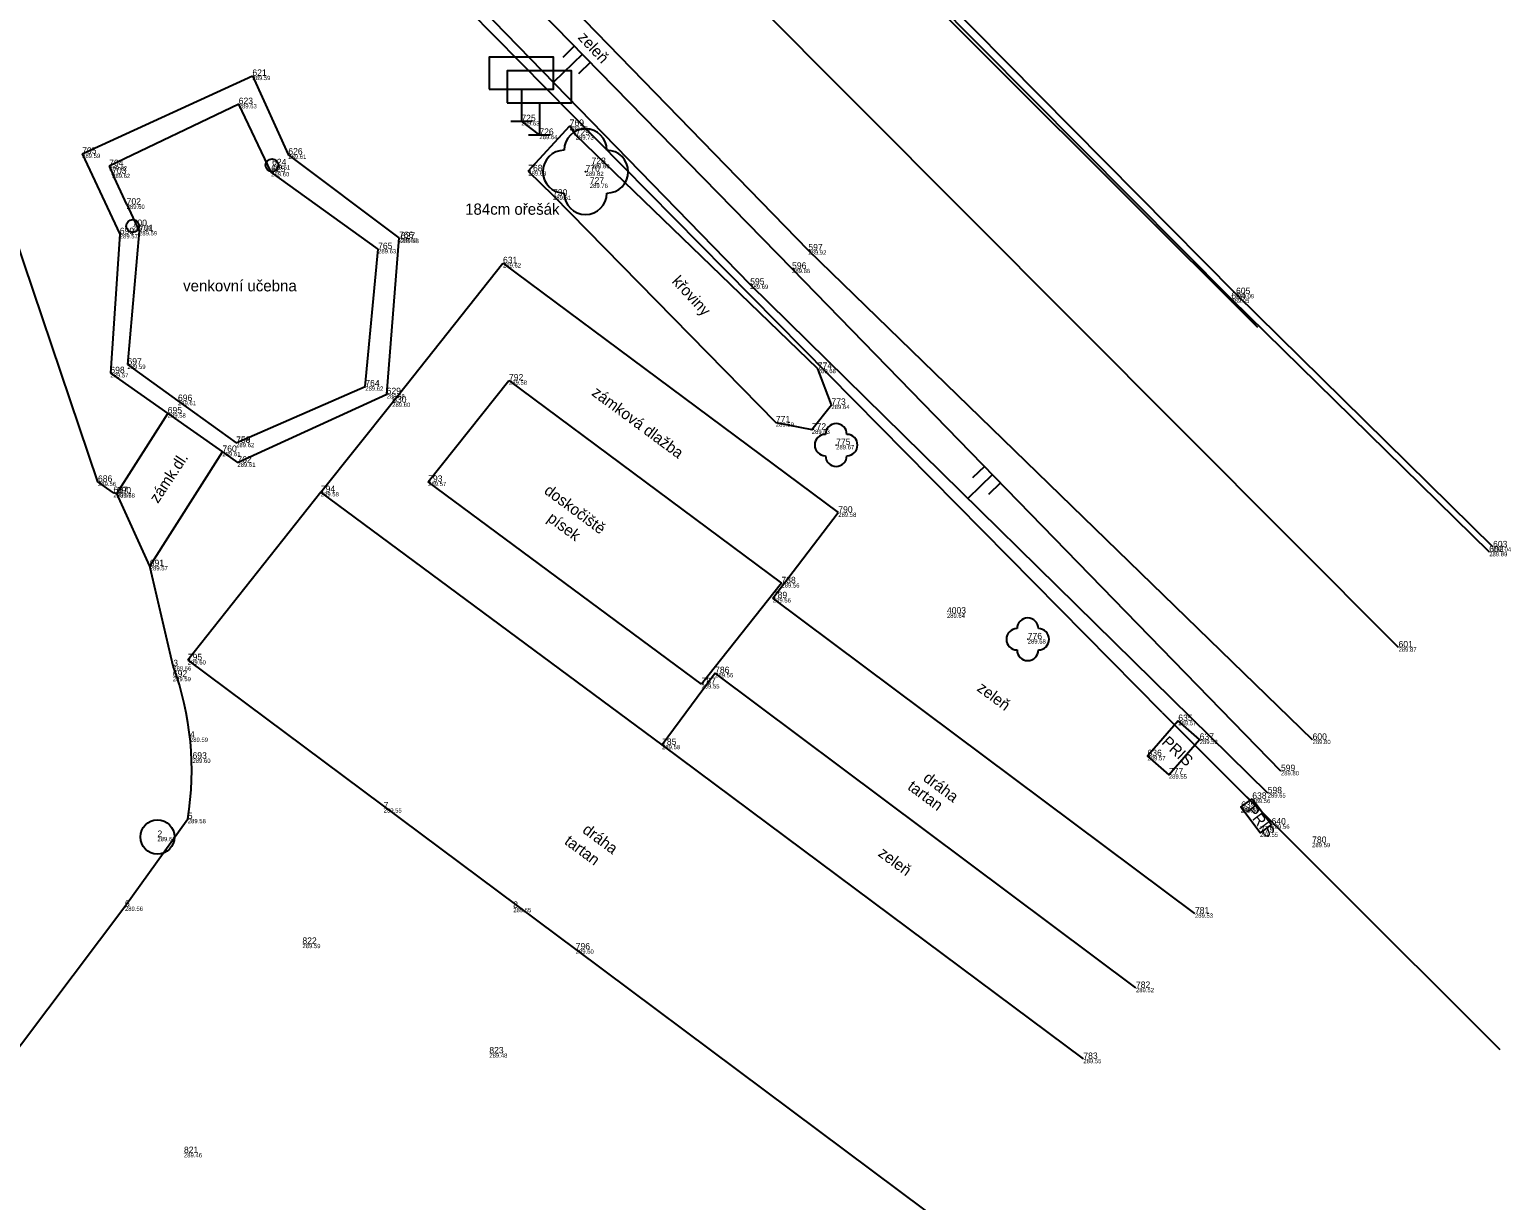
# Model space of a CAD drawing. Extents: x -805057 to -804930, y -994399 to -994240.
# Drawn here: x -804979.61 to -804944.98, y -994342.6 to -994315.23 of the extents above; entities that cross this region are included whole.
import ezdxf

# ---------------------------------------------------------------- set-up
doc = ezdxf.new("R2010")
doc.units = 0
for name, color, linetype in [('bod cislo', 7, 'Continuous'), ('bod pozice', 7, 'Continuous'), ('bod výška', 7, 'Continuous'), ('budova', 7, 'Continuous'), ('kanalizace', 7, 'Continuous'), ('Katastralni mapa', 7, 'Continuous'), ('komunikace', 7, 'Continuous'), ('plot', 7, 'Continuous'), ('popis', 7, 'Continuous'), ('PRIS', 7, 'Continuous'), ('strom', 7, 'Continuous'), ('svah', 7, 'Continuous'), ('svod', 7, 'Continuous'), ('značka', 7, 'Continuous'), ('šrafy', 7, 'Continuous')]:
    doc.layers.add(name, color=color, linetype=linetype)

msp = doc.modelspace()

# ---------------------------------------------------------------- linework, layer by layer
at = {"layer": 'bod pozice'}
for p, q in [((-804974.4, -994316.31), (-804974.4, -994316.31)), ((-804974.72, -994316.97), (-804974.72, -994316.97)), ((-804968.11, -994317.37), (-804968.11, -994317.37)), ((-804967.69, -994317.69), (-804967.69, -994317.69)), ((-804966.98, -994317.48), (-804966.98, -994317.48)), ((-804966.84, -994317.7), (-804966.84, -994317.7)), ((-804978.38, -994318.13), (-804978.38, -994318.13)), ((-804973.94, -994318.4), (-804973.94, -994318.4)), ((-804973.56, -994318.15), (-804973.56, -994318.15)), ((-804966.47, -994318.37), (-804966.47, -994318.37)), ((-804977.75, -994318.42), (-804977.75, -994318.42)), ((-804977.68, -994318.6), (-804977.68, -994318.6)), ((-804973.96, -994318.56), (-804973.96, -994318.56)), ((-804967.95, -994318.54), (-804967.95, -994318.54)), ((-804966.61, -994318.55), (-804966.61, -994318.55)), ((-804966.51, -994318.83), (-804966.51, -994318.83)), ((-804977.34, -994319.32), (-804977.34, -994319.32)), ((-804967.37, -994319.11), (-804967.37, -994319.11)), ((-804977.5, -994320.01), (-804977.5, -994320.01)), ((-804977.2, -994319.82), (-804977.2, -994319.82)), ((-804977.05, -994319.94), (-804977.05, -994319.94)), ((-804970.97, -994320.1), (-804970.97, -994320.1)), ((-804970.93, -994320.12), (-804970.93, -994320.12)), ((-804971.46, -994320.36), (-804971.46, -994320.36)), ((-804961.4, -994320.39), (-804961.4, -994320.39)), ((-804968.54, -994320.69), (-804968.54, -994320.69)), ((-804961.78, -994320.82), (-804961.78, -994320.82)), ((-804962.76, -994321.19), (-804962.76, -994321.19)), ((-804951.51, -994321.52), (-804951.51, -994321.52)), ((-804951.4, -994321.41), (-804951.4, -994321.41)), ((-804977.32, -994323.06), (-804977.32, -994323.06)), ((-804961.18, -994323.16), (-804961.18, -994323.16)), ((-804977.72, -994323.26), (-804977.72, -994323.26)), ((-804971.76, -994323.57), (-804971.76, -994323.57)), ((-804968.4, -994323.43), (-804968.4, -994323.43)), ((-804976.14, -994323.91), (-804976.14, -994323.91)), ((-804971.26, -994323.75), (-804971.26, -994323.75)), ((-804976.38, -994324.2), (-804976.38, -994324.2)), ((-804971.13, -994323.95), (-804971.13, -994323.95)), ((-804960.86, -994324), (-804960.86, -994324)), ((-804962.16, -994324.41), (-804962.16, -994324.41)), ((-804961.32, -994324.58), (-804961.32, -994324.58)), ((-804974.78, -994324.89), (-804974.78, -994324.89)), ((-804974.78, -994324.89), (-804974.78, -994324.89)), ((-804960.75, -994324.94), (-804960.75, -994324.94)), ((-804975.1, -994325.1), (-804975.1, -994325.1)), ((-804974.75, -994325.35), (-804974.75, -994325.35)), ((-804978.01, -994325.8), (-804978.01, -994325.8)), ((-804970.29, -994325.8), (-804970.29, -994325.8)), ((-804977.65, -994326.06), (-804977.65, -994326.06)), ((-804977.57, -994326.07), (-804977.57, -994326.07)), ((-804972.8, -994326.04), (-804972.8, -994326.04)), ((-804960.7, -994326.52), (-804960.7, -994326.52)), ((-804945.39, -994327.33), (-804945.39, -994327.33)), ((-804945.48, -994327.44), (-804945.48, -994327.44)), ((-804976.8, -994327.77), (-804976.8, -994327.77)), ((-804962.03, -994328.17), (-804962.03, -994328.17)), ((-804962.23, -994328.52), (-804962.23, -994328.52)), ((-804958.16, -994328.88), (-804958.16, -994328.88)), ((-804956.27, -994329.48), (-804956.27, -994329.48)), ((-804947.6, -994329.67), (-804947.6, -994329.67)), ((-804976.25, -994330.11), (-804976.25, -994330.11)), ((-804975.91, -994329.97), (-804975.91, -994329.97)), ((-804976.26, -994330.36), (-804976.26, -994330.36)), ((-804963.58, -994330.27), (-804963.58, -994330.27)), ((-804963.9, -994330.53), (-804963.9, -994330.53)), ((-804952.75, -994331.39), (-804952.75, -994331.39)), ((-804975.86, -994331.78), (-804975.86, -994331.78)), ((-804952.25, -994331.83), (-804952.25, -994331.83)), ((-804949.61, -994331.83), (-804949.61, -994331.83)), ((-804964.82, -994331.95), (-804964.82, -994331.95)), ((-804953.47, -994332.21), (-804953.47, -994332.21)), ((-804975.8, -994332.27), (-804975.8, -994332.27)), ((-804950.35, -994332.56), (-804950.35, -994332.56)), ((-804952.97, -994332.64), (-804952.97, -994332.64)), ((-804951.02, -994333.21), (-804951.02, -994333.21)), ((-804950.66, -994333.08), (-804950.66, -994333.08)), ((-804971.33, -994333.43), (-804971.33, -994333.43)), ((-804951.28, -994333.42), (-804951.28, -994333.42)), ((-804975.91, -994333.68), (-804975.91, -994333.68)), ((-804950.57, -994333.81), (-804950.57, -994333.81)), ((-804976.62, -994334.1), (-804976.62, -994334.1)), ((-804950.84, -994334), (-804950.84, -994334)), ((-804949.62, -994334.24), (-804949.62, -994334.24)), ((-804977.38, -994335.73), (-804977.38, -994335.73)), ((-804968.3, -994335.76), (-804968.3, -994335.76)), ((-804952.36, -994335.89), (-804952.36, -994335.89)), ((-804973.23, -994336.6), (-804973.23, -994336.6)), ((-804966.84, -994336.73), (-804966.84, -994336.73)), ((-804953.74, -994337.63), (-804953.74, -994337.63)), ((-804968.86, -994339.16), (-804968.86, -994339.16)), ((-804954.97, -994339.29), (-804954.97, -994339.29)), ((-804976, -994341.49), (-804976, -994341.49))]:
    msp.add_line(p, q, dxfattribs=at)
at = {"layer": 'budova'}
for p, q in [((-804974.72, -994316.97), (-804977.75, -994318.42)), ((-804973.96, -994318.56), (-804974.72, -994316.97)), ((-804977.75, -994318.42), (-804977.669, -994318.595)), ((-804977.336, -994319.318), (-804977.669, -994318.595)), ((-804971.46, -994320.36), (-804973.96, -994318.56)), ((-804977.336, -994319.318), (-804977.05, -994319.94)), ((-804977.05, -994319.94), (-804977.32, -994323.06)), ((-804971.76, -994323.57), (-804971.46, -994320.36)), ((-804977.32, -994323.06), (-804976.14, -994323.91)), ((-804974.78, -994324.89), (-804971.76, -994323.57)), ((-804976.14, -994323.91), (-804974.78, -994324.89))]:
    msp.add_line(p, q, dxfattribs=at)
at = {"layer": 'kanalizace'}
msp.add_circle((-804976.62, -994334.1), 0.4, dxfattribs=at)
at = {"layer": 'Katastralni mapa'}
msp.add_line((-804953.13, -994331.19), (-804945.235, -994339.07), dxfattribs=at)
for points in [[(-804953.13, -994331.19), (-804983.74, -994300.19)], [(-804963.19, -994309.92), (-804950.9, -994322.183)], [(-804953.13, -994331.19), (-804950.9, -994333.417)]]:
    msp.add_lwpolyline(points, dxfattribs=at)
at = {"layer": 'komunikace'}
for p, q in [((-804961.4, -994320.39), (-804971.33, -994310.17)), ((-804960.65, -994312.32), (-804951.51, -994321.52)), ((-804951.4, -994321.41), (-804960.54, -994312.18)), ((-804947.6, -994329.67), (-804962.86, -994314.37)), ((-804978.38, -994318.13), (-804974.4, -994316.31)), ((-804974.4, -994316.31), (-804973.56, -994318.15)), ((-804978.38, -994318.13), (-804977.5, -994320.01)), ((-804970.97, -994320.1), (-804973.56, -994318.15)), ((-804978.01, -994325.8), (-804980.44, -994318.62)), ((-804977.5, -994320.01), (-804977.72, -994323.26)), ((-804971.26, -994323.75), (-804970.97, -994320.1)), ((-804949.61, -994331.83), (-804961.4, -994320.39)), ((-804971.13, -994323.95), (-804968.54, -994320.69)), ((-804968.54, -994320.69), (-804960.7, -994326.52)), ((-804951.51, -994321.52), (-804945.48, -994327.44)), ((-804945.39, -994327.33), (-804951.4, -994321.41)), ((-804977.72, -994323.26), (-804976.38, -994324.2)), ((-804970.29, -994325.8), (-804968.4, -994323.43)), ((-804968.4, -994323.43), (-804962.03, -994328.17)), ((-804974.75, -994325.35), (-804971.26, -994323.75)), ((-804977.57, -994326.07), (-804976.38, -994324.2)), ((-804972.8, -994326.04), (-804971.13, -994323.95)), ((-804976.8, -994327.77), (-804975.1, -994325.1)), ((-804977.65, -994326.06), (-804978.01, -994325.8)), ((-804963.9, -994330.53), (-804970.29, -994325.8)), ((-804977.57, -994326.07), (-804977.65, -994326.06)), ((-804976.8, -994327.77), (-804977.57, -994326.07)), ((-804972.8, -994326.04), (-804975.91, -994329.97)), ((-804964.82, -994331.95), (-804972.8, -994326.04)), ((-804962.23, -994328.52), (-804960.7, -994326.52)), ((-804976.25, -994330.11), (-804976.8, -994327.77)), ((-804962.03, -994328.17), (-804963.9, -994330.53)), ((-804952.36, -994335.89), (-804962.23, -994328.52)), ((-804975.91, -994329.97), (-804966.84, -994336.73)), ((-804963.58, -994330.27), (-804964.82, -994331.95)), ((-804953.74, -994337.63), (-804963.58, -994330.27)), ((-804954.97, -994339.29), (-804964.82, -994331.95)), ((-804977.38, -994335.73), (-804975.91, -994333.68)), ((-804981.43, -994341.09), (-804977.38, -994335.73)), ((-804966.84, -994336.73), (-804958.03, -994343.31))]:
    msp.add_line(p, q, dxfattribs=at)
msp.add_lwpolyline([(-804976.38, -994324.2), (-804975.1, -994325.1), (-804974.75, -994325.35)], dxfattribs=at)
msp.add_ellipse((-804982.852, -994332.543), major_axis=(-0.23, 7.058), ratio=0.996025, start_param=4.518305, end_param=5.031767, dxfattribs=at)
at = {"layer": 'plot'}
for p, q in [((-804962.76, -994321.19), (-804972.34, -994311.34)), ((-804950.66, -994333.08), (-804962.76, -994321.19))]:
    msp.add_line(p, q, dxfattribs=at)
at = {"layer": 'PRIS'}
for points in [[(-804952.75, -994331.39), (-804953.47, -994332.21), (-804952.974, -994332.645), (-804952.254, -994331.825)], [(-804951.02, -994333.21), (-804950.57, -994333.81), (-804950.834, -994334.008), (-804951.284, -994333.408)]]:
    msp.add_lwpolyline(points, close=True, dxfattribs=at)
at = {"layer": 'strom'}
for p, q in [((-804967.95, -994318.54), (-804966.98, -994317.48)), ((-804966.84, -994317.7), (-804966.98, -994317.48)), ((-804961.18, -994323.16), (-804966.84, -994317.7)), ((-804967.95, -994318.54), (-804967.37, -994319.11)), ((-804967.37, -994319.11), (-804967.37, -994319.11)), ((-804967.37, -994319.11), (-804962.16, -994324.41)), ((-804960.86, -994324), (-804961.18, -994323.16)), ((-804961.32, -994324.58), (-804960.86, -994324)), ((-804962.16, -994324.41), (-804961.32, -994324.58))]:
    msp.add_line(p, q, dxfattribs=at)
for centre, radius in [((-804966.61, -994318.55), 0.0005), ((-804960.75, -994324.94), 0.00025), ((-804956.27, -994329.48), 0.00025)]:
    msp.add_circle(centre, radius, dxfattribs=at)
for centre, radius, start, end in [((-804966.61, -994318.05), 0.5, 0, 180), ((-804967.11, -994318.55), 0.5, 90, 270), ((-804966.11, -994318.55), 0.5, 270, 90), ((-804966.61, -994319.05), 0.5, 180, 360), ((-804960.75, -994324.69), 0.25, 0, 180), ((-804961, -994324.94), 0.25, 90, 270), ((-804960.5, -994324.94), 0.25, 270, 90), ((-804960.75, -994325.19), 0.25, 180, 360), ((-804956.27, -994329.23), 0.25, 0, 180), ((-804956.52, -994329.48), 0.25, 90, 270), ((-804956.02, -994329.48), 0.25, 270, 90), ((-804956.27, -994329.73), 0.25, 180, 360)]:
    msp.add_arc(centre, radius, start, end, dxfattribs=at)
at = {"layer": 'svah'}
for p, q in [((-804961.78, -994320.82), (-804971.58, -994310.78)), ((-804950.35, -994332.56), (-804961.78, -994320.82))]:
    msp.add_line(p, q, dxfattribs=at)
at = {"layer": 'svod'}
for centre in [(-804973.94, -994318.4), (-804977.2, -994319.82)]:
    msp.add_circle(centre, 0.15, dxfattribs=at)
at = {"layer": 'značka'}
for p, q in [((-804968.11, -994316.62), (-804968.11, -994317.37)), ((-804967.69, -994316.94), (-804967.69, -994317.69)), ((-804968.36, -994317.37), (-804967.86, -994317.37)), ((-804967.69, -994317.69), (-804968.11, -994317.37)), ((-804967.94, -994317.69), (-804967.44, -994317.69))]:
    msp.add_line(p, q, dxfattribs=at)
for points in [[(-804968.86, -994316.62), (-804967.36, -994316.62), (-804967.36, -994315.87), (-804968.86, -994315.87)], [(-804968.44, -994316.94), (-804966.94, -994316.94), (-804966.94, -994316.19), (-804968.44, -994316.19)]]:
    msp.add_lwpolyline(points, close=True, dxfattribs=at)
at = {"layer": 'šrafy'}
for p, q in [((-804966.866, -994315.609), (-804967.144, -994315.879)), ((-804966.68, -994315.8), (-804967.36, -994316.46)), ((-804966.493, -994315.992), (-804966.773, -994316.263)), ((-804957.097, -994325.63), (-804957.673, -994326.189)), ((-804957.283, -994325.439), (-804957.561, -994325.709)), ((-804956.91, -994325.822), (-804957.19, -994326.093))]:
    msp.add_line(p, q, dxfattribs=at)

# ---------------------------------------------------------------- texts
at = {"layer": 'bod cislo'}
for s, p in [('621    ', (-804974.4, -994316.31)), ('623    ', (-804974.72, -994316.97)), ('725    ', (-804968.11, -994317.37)), ('769    ', (-804966.98, -994317.48)), ('726    ', (-804967.69, -994317.69)), ('729    ', (-804966.84, -994317.7)), ('705    ', (-804978.38, -994318.13)), ('626    ', (-804973.56, -994318.15)), ('704    ', (-804977.75, -994318.42)), ('624    ', (-804973.94, -994318.4)), ('768    ', (-804967.95, -994318.54)), ('770    ', (-804966.61, -994318.55)), ('728    ', (-804966.47, -994318.37)), ('703    ', (-804977.68, -994318.6)), ('625    ', (-804973.96, -994318.56)), ('727    ', (-804966.51, -994318.83)), ('730    ', (-804967.37, -994319.11)), ('702    ', (-804977.34, -994319.32)), ('700    ', (-804977.2, -994319.82)), ('701    ', (-804977.05, -994319.94)), ('699    ', (-804977.5, -994320.01)), ('766    ', (-804970.97, -994320.1)), ('627    ', (-804970.93, -994320.12)), ('765    ', (-804971.46, -994320.36)), ('597    ', (-804961.4, -994320.39)), ('631    ', (-804968.54, -994320.69)), ('596    ', (-804961.78, -994320.82)), ('595    ', (-804962.76, -994321.19)), ('604    ', (-804951.51, -994321.52)), ('605    ', (-804951.4, -994321.41)), ('698    ', (-804977.72, -994323.26)), ('697    ', (-804977.32, -994323.06)), ('774    ', (-804961.18, -994323.16)), ('764    ', (-804971.76, -994323.57)), ('629    ', (-804971.26, -994323.75)), ('792    ', (-804968.4, -994323.43)), ('696    ', (-804976.14, -994323.91)), ('630    ', (-804971.13, -994323.95)), ('773    ', (-804960.86, -994324)), ('695    ', (-804976.38, -994324.2)), ('771    ', (-804962.16, -994324.41)), ('772    ', (-804961.32, -994324.58)), ('760    ', (-804975.1, -994325.1)), ('758    ', (-804974.78, -994324.89)), ('759    ', (-804974.78, -994324.89)), ('775    ', (-804960.75, -994324.94)), ('762    ', (-804974.75, -994325.35)), ('686    ', (-804978.01, -994325.8)), ('793    ', (-804970.29, -994325.8)), ('687    ', (-804977.65, -994326.06)), ('690    ', (-804977.57, -994326.07)), ('794    ', (-804972.8, -994326.04)), ('790    ', (-804960.7, -994326.52)), ('602    ', (-804945.48, -994327.44)), ('603    ', (-804945.39, -994327.33)), ('691    ', (-804976.8, -994327.77)), ('788    ', (-804962.03, -994328.17)), ('789    ', (-804962.23, -994328.52)), ('4003    ', (-804958.16, -994328.88)), ('776    ', (-804956.27, -994329.48)), ('795    ', (-804975.91, -994329.97)), ('601    ', (-804947.6, -994329.67)), ('3    ', (-804976.25, -994330.11)), ('786    ', (-804963.58, -994330.27)), ('692    ', (-804976.26, -994330.36)), ('787    ', (-804963.9, -994330.53)), ('635    ', (-804952.75, -994331.39)), ('4    ', (-804975.86, -994331.78)), ('785    ', (-804964.82, -994331.95)), ('637    ', (-804952.25, -994331.83)), ('600    ', (-804949.61, -994331.83)), ('693    ', (-804975.8, -994332.27)), ('636    ', (-804953.47, -994332.21)), ('777    ', (-804952.97, -994332.64)), ('599    ', (-804950.35, -994332.56)), ('598    ', (-804950.66, -994333.08)), ('7    ', (-804971.33, -994333.43)), ('639    ', (-804951.28, -994333.42)), ('638    ', (-804951.02, -994333.21)), ('5    ', (-804975.91, -994333.68)), ('2    ', (-804976.62, -994334.1)), ('779    ', (-804950.84, -994334)), ('640    ', (-804950.57, -994333.81)), ('780    ', (-804949.62, -994334.24)), ('6    ', (-804977.38, -994335.73)), ('8    ', (-804968.3, -994335.76)), ('781    ', (-804952.36, -994335.89)), ('822    ', (-804973.23, -994336.6)), ('796    ', (-804966.84, -994336.73)), ('782    ', (-804953.74, -994337.63)), ('823    ', (-804968.86, -994339.16)), ('783    ', (-804954.97, -994339.29)), ('821    ', (-804976, -994341.49))]:
    msp.add_text(s, height=0.15, dxfattribs=at).set_placement(p)
at = {"layer": 'bod výška'}
for s, p in [('289.59  ', (-804974.4, -994316.41)), ('289.63  ', (-804974.72, -994317.07)), ('289.63  ', (-804968.11, -994317.47)), ('289.64  ', (-804967.69, -994317.79)), ('289.68  ', (-804966.98, -994317.58)), ('289.73  ', (-804966.84, -994317.8)), ('289.59  ', (-804978.38, -994318.23)), ('289.61  ', (-804973.94, -994318.5)), ('289.61  ', (-804973.56, -994318.25)), ('289.80  ', (-804966.47, -994318.47)), ('289.62  ', (-804977.75, -994318.52)), ('289.62  ', (-804977.68, -994318.7)), ('289.60  ', (-804973.96, -994318.66)), ('289.63  ', (-804967.95, -994318.64)), ('289.82  ', (-804966.61, -994318.65)), ('289.76  ', (-804966.51, -994318.93)), ('289.60  ', (-804977.34, -994319.42)), ('289.61  ', (-804967.37, -994319.21)), ('289.57  ', (-804977.5, -994320.11)), ('289.59  ', (-804977.2, -994319.92)), ('289.59  ', (-804977.05, -994320.04)), ('289.63  ', (-804970.97, -994320.2)), ('289.63  ', (-804970.93, -994320.22)), ('289.63  ', (-804971.46, -994320.46)), ('289.92  ', (-804961.4, -994320.49)), ('289.62  ', (-804968.54, -994320.79)), ('289.86  ', (-804961.78, -994320.92)), ('289.69  ', (-804962.76, -994321.29)), ('289.95  ', (-804951.51, -994321.62)), ('290.09  ', (-804951.4, -994321.51)), ('289.59  ', (-804977.32, -994323.16)), ('289.68  ', (-804961.18, -994323.26)), ('289.57  ', (-804977.72, -994323.36)), ('289.62  ', (-804971.76, -994323.67)), ('289.58  ', (-804968.4, -994323.53)), ('289.61  ', (-804976.14, -994324.01)), ('289.58  ', (-804971.26, -994323.85)), ('289.58  ', (-804976.38, -994324.3)), ('289.60  ', (-804971.13, -994324.05)), ('289.64  ', (-804960.86, -994324.1)), ('289.59  ', (-804962.16, -994324.51)), ('289.63  ', (-804961.32, -994324.68)), ('289.62  ', (-804974.78, -994324.99)), ('289.62  ', (-804974.78, -994324.99)), ('289.67  ', (-804960.75, -994325.04)), ('289.61  ', (-804975.1, -994325.2)), ('289.61  ', (-804974.75, -994325.45)), ('289.56  ', (-804978.01, -994325.9)), ('289.57  ', (-804970.29, -994325.9)), ('289.57  ', (-804977.65, -994326.16)), ('289.58  ', (-804977.57, -994326.17)), ('289.58  ', (-804972.8, -994326.14)), ('289.58  ', (-804960.7, -994326.62)), ('290.04  ', (-804945.39, -994327.43)), ('289.89  ', (-804945.48, -994327.54)), ('289.57  ', (-804976.8, -994327.87)), ('289.56  ', (-804962.03, -994328.27)), ('289.56  ', (-804962.23, -994328.62)), ('289.64  ', (-804958.16, -994328.98)), ('289.68  ', (-804956.27, -994329.58)), ('289.87  ', (-804947.6, -994329.77)), ('289.56  ', (-804976.25, -994330.21)), ('289.60  ', (-804975.91, -994330.07)), ('289.59  ', (-804976.26, -994330.46)), ('289.56  ', (-804963.58, -994330.37)), ('289.55  ', (-804963.9, -994330.63)), ('289.57  ', (-804952.75, -994331.49)), ('289.59  ', (-804975.86, -994331.88)), ('289.52  ', (-804952.25, -994331.93)), ('289.80  ', (-804949.61, -994331.93)), ('289.58  ', (-804964.82, -994332.05)), ('289.57  ', (-804953.47, -994332.31)), ('289.60  ', (-804975.8, -994332.37)), ('289.80  ', (-804950.35, -994332.66)), ('289.55  ', (-804952.97, -994332.74)), ('289.56  ', (-804951.02, -994333.31)), ('289.65  ', (-804950.66, -994333.18)), ('289.55  ', (-804971.33, -994333.53)), ('289.57  ', (-804951.29, -994333.53)), ('289.59  ', (-804951.28, -994333.52)), ('289.58  ', (-804975.91, -994333.78)), ('289.56  ', (-804950.57, -994333.91)), ('289.61  ', (-804976.62, -994334.2)), ('289.55  ', (-804950.84, -994334.1)), ('289.59  ', (-804949.62, -994334.34)), ('289.56  ', (-804977.38, -994335.83)), ('289.55  ', (-804968.3, -994335.86)), ('289.53  ', (-804952.36, -994335.99)), ('289.59  ', (-804973.23, -994336.7)), ('289.60  ', (-804966.84, -994336.83)), ('289.52  ', (-804953.74, -994337.73)), ('289.48  ', (-804968.86, -994339.26)), ('289.55  ', (-804954.97, -994339.39)), ('289.46  ', (-804976, -994341.59))]:
    msp.add_text(s, height=0.1, dxfattribs=at).set_placement(p)
at = {"layer": 'popis'}
for s, height, rotation, p in [('zeleň', 0.2629, 313.0307, (-804966.804, -994315.427)), ('křoviny', 0.2629, 312.8096, (-804964.606, -994321.128)), ('zámková dlažba', 0.26289, 323.5379, (-804966.486, -994323.76)), ('zámk.dl.', 0.2629, 56.5528, (-804976.61, -994326.32)), ('doskočiště', 0.2629, 323.5379, (-804967.6, -994326.053)), ('písek', 0.2629, 323.5379, (-804967.526, -994326.7)), ('zeleň', 0.2629, 323.5379, (-804957.478, -994330.666)), ('PRIS', 0.2629, 317.0552, (-804953.156, -994331.911)), ('tartan', 0.2629, 323.5379, (-804959.1, -994332.97)), ('dráha', 0.2629, 323.5379, (-804958.738, -994332.771)), ('PRIS', 0.2629, 307.2443, (-804951.176, -994333.485)), ('dráha', 0.2629, 323.5379, (-804966.703, -994333.983)), ('tartan', 0.2629, 323.5379, (-804967.124, -994334.247)), ('zeleň', 0.2629, 323.5379, (-804959.789, -994334.527))]:
    msp.add_text(s, height=height, rotation=rotation, dxfattribs=at).set_placement(p)
for s, p in [('184cm ořešák', (-804969.426, -994319.557)), ('venkovní učebna', (-804976.02, -994321.348))]:
    msp.add_text(s, height=0.26289, dxfattribs=at).set_placement(p)

doc.saveas('drawing.dxf')
